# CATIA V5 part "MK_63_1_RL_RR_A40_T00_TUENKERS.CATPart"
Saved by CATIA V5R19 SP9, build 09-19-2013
Part number: MK_63_1_RL_RR_A40_T00_TUENKERS
Material "MISCHDICHTE": density 4989.5 kg/m3, Young's modulus 2e+11 Pa, Poisson ratio 0.266
Bounding box of the stored display mesh (mm): x -193.5 to 132.266, y -100.5 to 144, z -122.161 to 122.161
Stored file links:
  G:\Konstruktion\Modelle\Catia_V5\MK_63_1_RL_RR_A40_T00_TUENKERS.CATPart
  G:\Konstruktion\Modelle\Catia_V5\MK2_63_1_A40_T12_TUENKERS.CATPart
  C:\Catia\Tuenkers_B19SP9HF86_64\win_b64\reffiles\standard\MetricThickPitch.txt
  G:\Konstruktion\Modelle\Catia_V5\MK_63_1_A10_T12_TUENKERS.CATPart
  G:\Konstruktion\Modelle\Catia_V5\V2_63_1_BR3_ZL_ZR_RL_RR_A40_T12_TUENKERS.CATPart
  HANDHEBEL_KPL_50_63_TUENKERS.CATPart
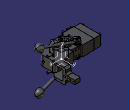
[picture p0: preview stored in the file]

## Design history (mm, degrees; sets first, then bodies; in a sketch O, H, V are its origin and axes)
AxisSystem1: origin (0, 0, 0), X (1, 0, 0), Y (0, 1, 0), Z (0, 0, 1)
Body1 (main body)
  Body2 "*DIT1\\*DIT3"
    Solid1 "Solid.1": solid without history
  Assemble1: tool Body2
  Body3 "*DIT1\\*DIT12\\*DIT16\\"
    Solid2 "Solid.1": solid without history
  Assemble2: tool Body3
  Body4 "*DIT1\\*DIT12\\*DIT17\\"
    Solid3 "Solid.1": solid without history
  Assemble3: tool Body4
  Body5 "*DIT1\\*DIT12\\MK_MK2_63_1_A10_A11_A12_T12_081112_3D_xSET4_2.1"
    Solid4 "Solid.1": solid without history
    Body6 "*DIT1\\*DIT12\\MK_MK2_63_1_A10_A11_A12_T12_081112_3D_xSET4_2.1\\Body.11 ( *SOL16 - wsp GEHAEUSE -  )"
      Solid5 "Solid.1": solid without history
    Add1 "*DIT1\\*DIT12\\MK_MK2_63_1_A10_A11_A12_T12_081112_3D_xSET4_2.1\\Body.11 ( *SOL16 - wsp GEHAEUSE -  )": tool Body6
    Body7 "*DIT1\\*DIT12\\MK_MK2_63_1_A10_A11_A12_T12_081112_3D_xSET4_2.1\\Body.12 ( *SOL17 - wsp GEHAEUSE -  )"
      Solid6 "Solid.1": solid without history
    Add2 "*DIT1\\*DIT12\\MK_MK2_63_1_A10_A11_A12_T12_081112_3D_xSET4_2.1\\Body.12 ( *SOL17 - wsp GEHAEUSE -  )": tool Body7
    Body8 "*DIT1\\*DIT12\\MK_MK2_63_1_A10_A11_A12_T12_081112_3D_xSET4_2.1\\Body.14 ( *SOL18 - wsp GEHAEUSE -  )"
      Solid7 "Solid.1": solid without history
    Add3 "*DIT1\\*DIT12\\MK_MK2_63_1_A10_A11_A12_T12_081112_3D_xSET4_2.1\\Body.14 ( *SOL18 - wsp GEHAEUSE -  )": tool Body8
  Assemble4: tool Body5
  Body9 "*DIT1\\MK_MK2_63_1_A10_A11_A12_T12_081112_3D_xSET2_1.1"
    Solid8 "Solid.1": solid without history
    Sketch1 on face of Solid8, origin (0, 0, 91.5), H (1, 0, 0), V (0, 1, 0)
      line L1 (-107.5, 25) -> (-93.5, 25)
      line L2 (-93.5, 25) -> (-93.5, -25)
      line L3 (-93.5, -25) -> (-107.5, -25)
      line L4 (-107.5, -25) -> (-107.5, 25)
      reference projected line E1 (-93.5, 25) -> (-93.5, -25) from edge [face of Solid8 | face of Solid8]
      reference projected line E2 (-150.5, 25) -> (-93.5, 25) from edge [face of Solid8 | face of Solid8]
      reference projected line E3 (-150.5, -25) -> (-93.5, -25) from edge [face of Solid8 | face of Solid8]
      line L5 (-137.2, 25) -> (-125.7, 25)
      line L6 (-125.7, 25) -> (-125.7, -5)
      line L7 (-125.7, -5) -> (-137.2, -5)
      line L8 (-137.2, -5) -> (-137.2, 25)
      reference projected line E4 (-150.5, 25) -> (-93.5, 25) from edge [face of Solid8 | face of Solid8]
      distance L2 E1 = 0
      distance L1 E2 = 0
      distance E3 L3 = 0
      distance L4 L2 = 14
      distance L6 L4 = 18.2
      distance L5 E4 = 0
      distance L8 L6 = 11.5
      distance L7 L5 = 30
      horizontal: L1 H, L3 H, L5 H, L7 H
      vertical: L2 V, L4 V, L6 V, L8 V
    Pad1: profile Sketch1, direction (0, 0, 1), length 9
    Chamfer1: length 9, angle 45, on edge [face of Pad1 from Sketch1.L8 | end face of Pad1]
    Chamfer2: length 10.5, angle 45, on edge [face of Pad1 | end face of Pad1]
  Assemble5: tool Body9
  Rotate1: Axis edge [XY plane of AxisSystem1 | ZX plane of AxisSystem1], Angle 90, ToTransfor Assemble5
  Body10
    Body11 "*DIT1\\MK_MK2_63_1_A10_A11_A12_T12_081112_3D_xSET2_1.1\\Body.2 ( *SOL2 - wsp MK_MK2 63_1 -  )"
      Solid9 "Solid.1": solid without history
    Assemble6: tool Body11
    Body12 "*DIT1\\MK_MK2_63_1_A10_A11_A12_T12_081112_3D_xSET2_1.1\\Body.3 ( *SOL3 - wsp MK_MK2 63_1 -  )"
      Solid10 "Solid.1": solid without history
    Assemble7: tool Body12
    Body13 "*DIT1\\MK_MK2_63_1_A10_A11_A12_T12_081112_3D_xSET2_1.1\\Body.4 ( *SOL4 - wsp MK_MK2 63_1 -  )"
      Solid11 "Solid.1": solid without history
    Assemble8: tool Body13
    Body14 "*DIT1\\MK_MK2_63_1_A10_A11_A12_T12_081112_3D_xSET2_1.1\\Body.5 ( *SOL5 - wsp MK_MK2 63_1 -  )"
      Solid12 "Solid.1": solid without history
    Assemble9: tool Body14
    Body15 "*DIT1\\MK_MK2_63_1_A10_A11_A12_T12_081112_3D_xSET2_1.1\\Body.6 ( *SOL6 - wsp MK_MK2 63_1 -  )"
      Solid13 "Solid.1": solid without history
    Assemble10: tool Body15
    Rotate2: Axis edge, Angle 90, ToTransfor Assemble10
    Translate1: Direction edge [YZ plane of AxisSystem1 | XY plane of AxisSystem1], Length -1, ToTransfor Rotate2
  Assemble11: tool Body10
Body16 "Spannarm_kpl_63_A40_242839_Tuenkers", material "Steel"
  Sketch2 on xy-plane, origin (0, 0, 0), H (1, 0, 0), V (0, 1, 0)
    line L1 (73, 144) -> (45, 144)
    arc A1 centre (53, 43.1005) radius 20 from (67.1421, 28.9584) to (73, 43.1005) ccw
    line L2 (67.1421, 28.9584) -> (19.0919, -19.0919)
    line L3 (10.9602, 10.9602) -> (10.9602, -10.9602)
    line L4 (10.9602, 10.9602) -> (-10.9602, 10.9602)
    line L5 (-19.0919, 19.0919) -> (-10.9602, 10.9602)
    line L6 (-1.4396, 36.7442) -> (-19.0919, 19.0919)
    line L7 (38.4202, 51.252) -> (-1.4396, 36.7442)
    arc A2 centre (35, 60.6489) radius 10 from (38.4202, 51.252) to (45, 60.6489) ccw
    line L8 (45, 60.6489) -> (45, 144)
    line L9 (73, 144) -> (73, 43.1005)
    line L10 (10.9602, -10.9602) -> (19.0919, -19.0919)
    point P7 (10.9602, 10.9602)
    point P10 (-1.4396, 36.7442)
    point P13 (73, 37.6447)
    point P14 (45, 51.7188)
    reference intersected line E1 through (0, 0) direction (-0.7071, 0.7071)
    reference intersected line E2 through (0, 0) direction (-0.7071, 0.7071)
    reference intersected line E3 through (0, 0) direction (-0.7071, 0.7071)
    reference intersected line E4 through (0, 0) direction (0, 1) from yz-plane
    reference intersected line E5 through (0, 0) direction (-1, 0) from zx-plane
    reference intersected line E6 through (0, 0) direction (0, 1) from yz-plane
    angle L6 L7 = 25
    radius A1 = 20
    angle L4 L5 = 45
    distance P7 L2 = 27
    distance L2 L6 = 54
    angle L2 L10 = 90
    distance P7 E1 = 15.5
    distance E4 L3 = 10.9602
    distance E5 L1 = 144
    distance E6 L8 = 45
    distance L9 L8 = 28
    radius A2 = 10
    distance P10 L1 = 107.2558
    tangency: A1 L2, L8 A2, A2 L7, L9 A1
    coincidence: L10 E2, L5 E3
  Pad2: profile Sketch2, direction (0, 0, 1), length 39, opposite side length 39
  Chamfer3: length 0.1, angle 45, on edge [face of Pad2 from Sketch2.L3 | end face of Pad2]; edge [face of Pad2 from Sketch2.L4 | end face of Pad2]; edge [start face of Pad2 | face of Pad2 from Sketch2.L4]; edge [start face of Pad2 | face of Pad2 from Sketch2.L3]
  Sketch3 on face of Pad2 from Sketch2.L9, origin (73, 0, 0), H (0, 1, 0), V (0, 0, 1)
    line L1 (144, -10) -> (144, 10)
    line L2 (103, 10) -> (144, 10)
    arc A1 centre (103, 18) radius 8 from (103, 10) to (95, 18) cw
    line L3 (95, 18) -> (95, 29)
    arc A2 centre (85, 29) radius 10 from (85, 39) to (95, 29) cw
    line L4 (-20, 39) -> (85, 39)
    line L5 (-20, 39) -> (-20, 27)
    line L6 (74, 27) -> (-20, 27)
    arc A3 centre (74, 21) radius 6 from (74, 27) to (80, 21) cw
    line L7 (80, 21) -> (80, -21)
    arc A4 centre (74, -21) radius 6 from (80, -21) to (74, -27) cw
    line L8 (-20, -27) -> (74, -27)
    line L9 (-20, -27) -> (-20, -39)
    line L10 (-20, -39) -> (85, -39)
    arc A5 centre (85, -29) radius 10 from (95, -29) to (85, -39) cw
    line L11 (95, -29) -> (95, -18)
    arc A6 centre (103, -18) radius 8 from (95, -18) to (103, -10) cw
    line L12 (103, -10) -> (144, -10)
    reference intersected line E1 through (0, 0) direction (-1, 0) from xy-plane
    reference intersected line E2 through (0, 0) direction (0, 1) from zx-plane
    reference intersected line E3 through (0, 0) direction (0, 1) from zx-plane
    reference intersected line E4 through (0, 0) direction (0, 1) from zx-plane
    line L13 (-30, -44) -> (160, -44)
    line L14 (160, -44) -> (160, 44)
    line L15 (160, 44) -> (-30, 44)
    line L16 (-30, 44) -> (-30, -44)
    reference intersected line E5 through (0, 0) direction (-1, 0) from xy-plane
    reference intersected line E6 through (0, 0) direction (0, 1) from zx-plane
    distance L12 E1 = 10
    distance L12 L2 = 20
    distance L4 L10 = 78
    distance L6 L8 = 54
    distance L10 L12 = 29
    distance L8 L10 = 12
    radius A3 = 6
    radius A4 = 6
    radius A5 = 10
    radius A2 = 10
    radius A1 = 8
    radius A6 = 8
    distance L7 E2 = 80
    distance L3 E3 = 95
    distance L1 L5 = 164
    distance E4 L1 = 144
    distance L16 L14 = 190
    distance L15 L13 = 88
    distance L13 E5 = 44
    distance L14 E6 = 160
    tangency: L6 A3, A3 L7, L7 A4, A4 L8, L10 A5, A5 L11, L3 A1, A1 L2, A6 L12, A2 L4, A2 L3, A6 L11
    vertical: L1 V, L14 V, L16 V
    horizontal: L12 H, L13 H, L15 H
    coincidence: L5 L9, L11 L3
  Pocket1: profile Sketch3, direction (-1, 0, 0), length 95
  Sketch4 on face of Pad2 from Sketch2.L9, origin (73, 131.0889, -0.3784), H (0, 1, 0), V (0, 0, 1)
    point P1 (3.9111, 0.3784)
    reference intersected line E1 through (0, 0.3784) direction (-1, 0) from xy-plane
    reference intersected line E2 through (-131.0889, 0) direction (0, 1) from zx-plane
    reference intersected line E3 through (-131.0889, 0) direction (0, 1) from zx-plane
    reference intersected line E4 (12.9111, -38.6216) -> (-87.9884, -38.6216) from start face of Pad2
    distance P1 E2 = 135
    distance E3 E4 = 0
    coincidence: P1 E1
  Hole1: placed by Sketch4, at (73, 135, 0) direction (-1, 0, 0), diameter 6, through (limit type 6)
  Sketch5 on face of Pad2 from Sketch2.L9, origin (73, 113.9529, 0.5693), H (0, 1, 0), V (0, 0, 1)
    point P1 (-8.9529, -0.5693)
    reference projected point E1 (21.0471, -0.5693) from axis of face of Hole1
    reference intersected line E2 through (0, -0.5693) direction (-1, 0) from xy-plane
    distance P1 E1 = 30
    coincidence: P1 E2
  Hole2: placed by Sketch5, at (73, 105, 0) direction (-1, 0, 0), diameter 6, through (limit type 6)
  Sketch6 on face of Pad2 from Sketch2.L9, origin (73, 123.4122, -0.1089), H (0, 1, 0), V (0, 0, 1)
    point P1 (-3.4122, 0.1089)
    reference projected point E1 (11.5878, 0.1089) from axis of face of Hole1
    reference projected point E2 (-18.4122, 0.1089) from axis of face of Hole2
    distance P1 E1 = 15
    distance E2 P1 = 15
  Hole3: placed by Sketch6, at (73, 120, 0) direction (-1, 0, 0), diameter 9, through (limit type 6)
  Sketch7 on face of Pad2 from Sketch2.L9, origin (73, 93.5248, 1.4062), H (0, 1, 0), V (0, 0, 1)
    point P1 (-3.5248, -1.4062)
    reference projected point E1 (26.4752, -1.4062) from axis of face of Hole3
    reference projected point E2 (11.4752, -1.4062) from axis of face of Hole2
    distance P1 E1 = 30
    distance P1 E2 = 15
  Hole4: placed by Sketch7, at (73, 90, 0) direction (-1, 0, 0), diameter 9, through (limit type 6)
  Sketch8 on face of Pad2 from Sketch2.L10, origin (13.7879, -13.7879, 28.7565), H (0.7071, -0.7071, 0), V (0, 0, 1)
    point P1 (0.5009, 4.2435)
    reference intersected line E1 through (0, -28.7565) direction (-1, 0) from xy-plane
    reference projected line E2 (-19.4991, -67.7565) -> (-19.4991, 10.2435) from edge [face of Pad2 from Sketch2.L3 | face of Pad2 from Sketch2.L4]
    distance P1 E1 = 33
    distance E2 P1 = 20
  Hole5: placed by Sketch8, at (14.1421, -14.1421, 33) direction (0.7071, 0.7071, 0), diameter 6.647, depth 18, V-bottom angle 120, threaded "M8", thread diameter 8, thread depth 15, pitch 1.25
  RectPattern1: of Hole5, direction 1 instances 2, spacing 66, along edge [face of Pad2 from Sketch2.L3 | face of Pad2 from Sketch2.L4] reversed, direction 2 instances 2, spacing 40, along edge [face of Pad2 from Sketch2.L10 | face of Pocket1] reversed
  Body17 "KLEMMFLANSCH KPL"
    Sketch9 on xy-plane, origin (0, 0, 0), H (1, 0, 0), V (0, 1, 0)
      line L1 (-20.5061, 17.6777) -> (-31.1375, 7.0463)
      line L2 (-31.1375, 7.0463) -> (-19.1167, -4.9745)
      line L3 (-19.1167, -4.9745) -> (-25.4806, -11.3385)
      line L4 (-25.4806, -11.3385) -> (-11.3385, -25.4806)
      line L5 (-11.3385, -25.4806) -> (-4.9745, -19.1167)
      line L6 (-4.9745, -19.1167) -> (7.0463, -31.1375)
      line L7 (7.0463, -31.1375) -> (19.0671, -19.1167)
      line L8 (19.0671, -19.1167) -> (10.9106, -10.9602)
      line L9 (10.9106, -10.9602) -> (-10.9602, -10.9602)
      point P10 (-10.9602, -10.9602)
      line L10 (-10.9602, -10.9602) -> (-10.9602, 8.1317)
      line L11 (-10.9602, 8.1317) -> (-20.5061, 17.6777)
      reference intersected line E1 through (0, 0) direction (-0.7071, 0.7071)
      reference intersected line E2 through (0, 0) direction (-0.7071, 0.7071)
      reference intersected line E3 through (0, 0) direction (-0.7071, -0.7071)
      distance L4 L8 = 26
      distance L7 L5 = 17
      distance L5 L3 = 20
      distance L7 L1 = 54
      distance L4 L6 = 9
      distance E1 P10 = 15.5
      distance L11 E2 = 2
      distance L11 L8 = 1.965
      angle L11 L10 = 135
      angle L9 L8 = 45
      distance L7 P10 = 27
      distance E3 L7 = 27
      coincidence: L2 L6
    Pad3: profile Sketch9, direction (0, 0, 1), length 39, opposite side length -27
    Chamfer4: length 0.1, angle 45, on edge [face of Pad3 from Sketch9.L9 | end face of Pad3]; edge [face of Pad3 from Sketch9.L10 | end face of Pad3]
    Sketch10 on face of Pad3 from Sketch9.L6, origin (-12.0456, -12.0456, 0), H (0.7071, -0.7071, 0), V (0, 0, 1)
      circle A1 centre (20, 33) radius 4
      point P1 (20, 33)
      circle A2 centre (-20, 33) radius 4
      point P2 (-20, 33)
      reference projected line E1 (-27, 27) -> (-10, 27) from edge [start face of Pad3 | face of Pad3 from Sketch9.L2]
      reference projected line E2 (10, 27) -> (27, 27) from edge [start face of Pad3 | face of Pad3 from Sketch9.L6]
      reference projected line E3 (27, 27) -> (27, 39) from edge [face of Pad3 from Sketch9.L7 | face of Pad3 from Sketch9.L6]
      reference projected line E4 (-27, 27) -> (-27, 39) from edge [face of Pad3 from Sketch9.L2 | face of Pad3 from Sketch9.L1]
      radius A1 = 4
      radius A2 = 4
      distance E1 P2 = 6
      distance P1 E2 = 6
      distance E3 P1 = 7
      distance P2 E4 = 7
    Pad4: profile Sketch10, direction (0.7071, 0.7071, 0), length 20
    Sketch11 on face of Pad4, origin (-12.0456, -12.0456, 0), H (0.7071, -0.7071, 0), V (0, 0, 1)
      circle A1 centre (20, 33) radius 6.5
      point P1 (20, 33)
      circle A2 centre (-20, 33) radius 6.5
      point P2 (-20, 33)
      reference projected line E1 (-27, 27) -> (-27, 39) from edge [face of Pad3 from Sketch9.L2 | face of Pad3 from Sketch9.L1]
      reference projected line E2 (27, 27) -> (27, 39) from edge [face of Pad3 from Sketch9.L7 | face of Pad3 from Sketch9.L6]
      reference projected line E3 (-27, 27) -> (-10, 27) from edge [start face of Pad3 | face of Pad3 from Sketch9.L2]
      reference projected line E4 (10, 27) -> (27, 27) from edge [start face of Pad3 | face of Pad3 from Sketch9.L6]
      radius A1 = 6.5
      radius A2 = 6.5
      distance E1 P2 = 7
      distance E2 P1 = 7
      distance E3 P2 = 6
      distance E4 P1 = 6
    Pad5: profile Sketch11, direction (-0.7071, -0.7071, 0), length 1.4
    Chamfer5: length 0.1, angle 45, on edge [face of Pad5 from Sketch11.A1 | end face of Pad5]; edge [face of Pad5 from Sketch11.A2 | end face of Pad5]
    Sketch12 on end face of Pad5, origin (-13.0355, -13.0355, 0), H (0.7071, -0.7071, 0), V (0, 0, 1)
      circle A1 centre (20, 33) radius 6.5
      point P1 (20, 33)
      circle A2 centre (-20, 33) radius 6.5
      point P2 (-20, 33)
      reference projected line E1 (10, 27) -> (27, 27) from edge [start face of Pad3 | face of Pad4]
      reference projected line E2 (27, 27) -> (27, 39) from edge [face of Pad3 from Sketch9.L7 | face of Pad3 from Sketch9.L6]
      reference projected line E3 (-27, 27) -> (-27, 39) from edge [face of Pad3 from Sketch9.L2 | face of Pad3 from Sketch9.L1]
      reference projected line E4 (-27, 27) -> (-10, 27) from edge [start face of Pad3 | face of Pad4]
      radius A1 = 6.5
      radius A2 = 6.5
      distance E1 P1 = 6
      distance E2 P1 = 7
      distance E3 P2 = 7
      distance E4 P2 = 6
    Pad6: profile Sketch12, direction (-0.7071, -0.7071, 0), length 8
    Fillet1: radius 0.5, on end face of Pad6; edge [face of Pad6 from Sketch12.A1 | end face of Pad6]
    Mirror1: of the body so far, about xy-plane, deactivated
  Assemble12: tool Body17
Body18 "ENDLAGENRASTE_LINKS"
  Solid14 "Manifold Solid #1213": solid without history
  Body19 "LUMP70"
    Solid15 "Manifold Solid #2778": solid without history
  Assemble13: tool Body19
  Body20 "LUMP73"
    Solid16 "Manifold Solid #4455": solid without history
  Assemble14: tool Body20
  Body21 "LUMP74"
    Solid17 "Manifold Solid #5598": solid without history
  Assemble15: tool Body21
  Body22 "LUMP76"
    Solid18 "Manifold Solid #7126": solid without history
  Assemble16: tool Body22
  Body23 "LUMP79"
    Solid19 "Manifold Solid #8329": solid without history
  Assemble17: tool Body23
  Body24 "LUMP81"
    Solid20 "Manifold Solid #8843": solid without history
  Assemble18: tool Body24
  Body25 "LUMP82"
    Solid21 "Manifold Solid #9252": solid without history
  Assemble19: tool Body25
  Body26 "LUMP85"
    Solid22 "Manifold Solid #10175": solid without history
  Assemble20: tool Body26
  Body27 "LUMP87"
    Solid23 "Manifold Solid #10993": solid without history
  Assemble21: tool Body27
  Body28 "LUMP88"
    Solid24 "Manifold Solid #11378": solid without history
  Assemble22: tool Body28
  Body29 "LUMP89"
    Solid25 "Manifold Solid #12146": solid without history
  Assemble23: tool Body29, deactivated
  Body30 "LUMP93"
    Solid26 "Manifold Solid #13965": solid without history
  Assemble24: tool Body30, deactivated
  Body31 "LUMP94"
    Solid27 "Manifold Solid #14222": solid without history
  Assemble25: tool Body31, deactivated
  Body32 "LUMP97"
    Solid28 "Manifold Solid #15145": solid without history
  Assemble26: tool Body32, deactivated
  Body33 "LUMP98"
    Solid29 "Manifold Solid #15554": solid without history
  Assemble27: tool Body33, deactivated
  Body34 "LUMP101"
    Solid30 "Manifold Solid #16781": solid without history
  Assemble28: tool Body34
  Body35 "LUMP102"
    Solid31 "Manifold Solid #17038": solid without history
  Assemble29: tool Body35
  Rotate3: Axis edge, Angle 90, ToTransfor Assemble29
Body36 "ENDLAGENRASTE_RECHTS"
  Body37 "LUMP69"
    Solid32 "Manifold Solid #2521": solid without history
  Assemble30: tool Body37
  Body38 "LUMP71"
    Solid33 "Manifold Solid #3035": solid without history
  Assemble31: tool Body38
  Body39 "LUMP72"
    Solid34 "Manifold Solid #3745": solid without history
  Assemble32: tool Body39
  Body40 "LUMP75"
    Solid35 "Manifold Solid #6741": solid without history
  Assemble33: tool Body40
  Body41 "LUMP77"
    Solid36 "Manifold Solid #7511": solid without history
  Assemble34: tool Body41
  Body42 "LUMP78"
    Solid37 "Manifold Solid #7920": solid without history
  Assemble35: tool Body42
  Body43 "LUMP80"
    Solid38 "Manifold Solid #8586": solid without history
  Assemble36: tool Body43
  Body44 "LUMP83"
    Solid39 "Manifold Solid #9661": solid without history
  Assemble37: tool Body44
  Body45 "LUMP84"
    Solid40 "Manifold Solid #9918": solid without history
  Assemble38: tool Body45
  Body46 "LUMP86"
    Solid41 "Manifold Solid #10584": solid without history
  Assemble39: tool Body46
  Body47 "LUMP90"
    Solid42 "Manifold Solid #12531": solid without history
  Assemble40: tool Body47
  Body48 "LUMP91"
    Solid43 "Manifold Solid #13299": solid without history
  Assemble41: tool Body48
  Body49 "LUMP92"
    Solid44 "Manifold Solid #13708": solid without history
  Assemble42: tool Body49
  Body50 "LUMP95"
    Solid45 "Manifold Solid #14479": solid without history
    Translate2: Direction edge [face of Solid43 | face of Solid43], Length -4, ToTransfor Solid45
  Assemble43: tool Body50
  Body51 "LUMP96"
    Solid46 "Manifold Solid #14736": solid without history
    Translate3: Direction edge [face of Solid43 | face of Solid43], Length -4, ToTransfor Solid46
  Assemble44: tool Body51
  Body52 "LUMP99"
    Solid47 "Manifold Solid #15963": solid without history
    Translate4: Direction edge [face of Solid43 | face of Solid43], Length -4, ToTransfor Solid47
  Assemble45: tool Body52
  Body53 "LUMP100"
    Solid48 "Manifold Solid #16372": solid without history
    Translate5: Direction edge [face of Solid43 | face of Solid43], Length -4, ToTransfor Solid48
  Assemble46: tool Body53
  Body54 "LUMP103"
    Solid49 "Manifold Solid #17295": solid without history
  Assemble47: tool Body54
  Rotate4: Axis edge, Angle 90, ToTransfor Assemble47
Body55 "Handhebel_KPL_218625_TUENKERS.1"
  Solid50: solid without history
  Body56 "Handhebel_KPL_218625_TUENKERS.2"
    Solid51: solid without history
  Assemble48: tool Body56
  Translate6: Direction edge [XY plane of AxisSystem1 | ZX plane of AxisSystem1], ToTransfor Assemble48, Length -86
  Translate7: Direction edge [ZX plane of AxisSystem1 | YZ plane of AxisSystem1], ToTransfor Translate6, Length 28
  Translate8: Direction edge [YZ plane of AxisSystem1 | XY plane of AxisSystem1], ToTransfor Translate7, Length -4
Body57 "Handhebel_KPL_218625_TUENKERS.1"
  Solid52: solid without history
  Body58 "Handhebel_KPL_218625_TUENKERS.2"
    Solid53: solid without history
  Assemble49: tool Body58
  Translate9: Direction edge [XY plane of AxisSystem1 | ZX plane of AxisSystem1], Length -86, ToTransfor Assemble49
  Translate10: Direction edge [ZX plane of AxisSystem1 | YZ plane of AxisSystem1], Length 28, ToTransfor Translate9
  Translate11: Direction edge [YZ plane of AxisSystem1 | XY plane of AxisSystem1], Length -4, ToTransfor Translate10
  Symmetry1: ToTransfor Translate11, Reference XY plane of AxisSystem1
